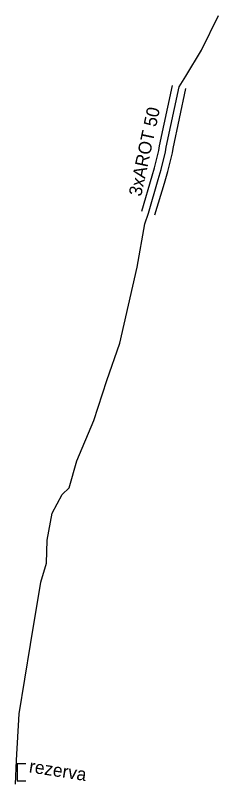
# Model space of a CAD drawing. Extents: x -651943 to -618711, y -1138561 to -1100552.
# Drawn here: x -649464.72 to -649452.92, y -1111520.46 to -1111475.93 of the extents above; entities that cross this region are included whole.
import ezdxf

# ---------------------------------------------------------------- set-up
doc = ezdxf.new("R2010")
doc.units = 0
doc.layers.add('KT trasa', color=7, linetype='Continuous')
doc.layers.add('KT zařízení', color=7, linetype='Continuous')

# ---------------------------------------------------------------- blocks, each defined once
blk = doc.blocks.new('TVREZ')
at = {"layer": 'KT zařízení'}
for p, q in [((-0.05, 0.05), (0, 0.05)), ((0, -0.05), (0, 0.05)), ((-0.05, -0.05), (0, -0.05))]:
    blk.add_line(p, q, dxfattribs=at)

msp = doc.modelspace()

# ---------------------------------------------------------------- linework, layer by layer
at = {"layer": 'KT trasa'}
for p, q in [((-649453.91, -1111477.94), (-649452.918, -1111475.926)), ((-649454.82, -1111479.45), (-649453.91, -1111477.94)), ((-649455.21, -1111480.08), (-649454.82, -1111479.45)), ((-649455.96, -1111483.58), (-649455.21, -1111480.08)), ((-649456, -1111483.84), (-649455.96, -1111483.58)), ((-649456.25, -1111484.88), (-649456, -1111483.84)), ((-649456.42, -1111485.46), (-649456.25, -1111484.88)), ((-649457, -1111487.4), (-649456.42, -1111485.46)), ((-649457.2, -1111488.03), (-649457, -1111487.4)), ((-649457.65, -1111490.54), (-649457.2, -1111488.03)), ((-649458.65, -1111494.96), (-649457.65, -1111490.54)), ((-649459.4, -1111497.12), (-649458.65, -1111494.96)), ((-649460.17, -1111499.45), (-649459.4, -1111497.12)), ((-649461.16, -1111501.79), (-649460.17, -1111499.45)), ((-649461.59, -1111503.36), (-649461.16, -1111501.79)), ((-649462.01, -1111503.73), (-649461.59, -1111503.36)), ((-649462.58, -1111504.82), (-649462.01, -1111503.73)), ((-649462.88, -1111506.38), (-649462.58, -1111504.82)), ((-649462.91, -1111507.73), (-649462.88, -1111506.38)), ((-649463.24, -1111508.82), (-649462.91, -1111507.73)), ((-649463.84, -1111512.44), (-649463.24, -1111508.82)), ((-649464.49, -1111516.47), (-649463.84, -1111512.44)), ((-649464.66, -1111519.15), (-649464.49, -1111516.47)), ((-649464.72, -1111520.56), (-649464.66, -1111519.15))]:
    msp.add_line(p, q, dxfattribs=at)
at = {"layer": 'KT zařízení'}
for p, q in [((-649456.353, -1111483.504), (-649455.601, -1111479.996)), ((-649455.566, -1111483.656), (-649454.818, -1111480.163)), ((-649456.393, -1111483.768), (-649456.353, -1111483.504)), ((-649456.635, -1111484.775), (-649456.393, -1111483.768)), ((-649455.864, -1111484.984), (-649455.606, -1111483.911)), ((-649455.606, -1111483.911), (-649455.566, -1111483.656)), ((-649456.773, -1111485.245), (-649456.635, -1111484.775)), ((-649457.383, -1111487.285), (-649456.773, -1111485.245)), ((-649456.066, -1111485.674), (-649455.864, -1111484.984)), ((-649456.616, -1111487.514), (-649456.066, -1111485.674))]:
    msp.add_line(p, q, dxfattribs=at)

# ---------------------------------------------------------------- block references
at = {"layer": 'KT zařízení', "xscale": 10.000000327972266, "yscale": 10.000000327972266, "rotation": 179.98532574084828}
msp.add_blockref('TVREZ', (-649464.61, -1111519.87), dxfattribs=at)

# ---------------------------------------------------------------- texts
at = {"layer": 'KT zařízení'}
for s, rotation, p in [('3xAROT 50', 77.9052, (-649457.416, -1111486.469)), ('rezerva', 351.2176, (-649463.958, -1111519.861))]:
    msp.add_text(s, height=0.75, rotation=rotation, dxfattribs=at).set_placement(p)

doc.saveas('drawing.dxf')
